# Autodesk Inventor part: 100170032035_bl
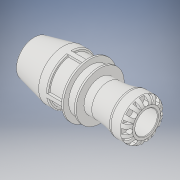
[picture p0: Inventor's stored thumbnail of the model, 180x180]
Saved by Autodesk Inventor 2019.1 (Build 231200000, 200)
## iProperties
Created: 2016-12
Part Number: 100170032035_bl
Material: PVC-Piping
Description: PLASSON UNIVERSAL COUPLING 31-35x32 SERIES 1
Document SubType Name: Modeling
Designer: KIM
Mass: 298.996 g
Surface Area: 569.061 cm^2
Volume: 213.568 cm^3
Density: 1.4 g/cm^3
Appearance: Smooth - White
Author: KIM
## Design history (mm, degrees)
derived "10017.ipt"
feature "Solid1::10017.ipt" dims "ScaleForDerivedMember" = 10
tag "TaggingFeature1"
body "Solid1"
other parameters: "d15" = 35 [user parameter], "d16" = 34.3 [user parameter], "d20" = 62.32 [user parameter], "d21" = 80 deg [user parameter], "d22" = 23 [user parameter], "d23" = 0 [user parameter], "d25" = 360 deg [user parameter], "d48" = 1.6 [user parameter], "d52" = 0.76 [user parameter], "d72" = 32 [user parameter], "d73" = 55 [user parameter], "d74" = 3.2 [user parameter], "d80" = 23.1 [user parameter], "d81" = 77 deg [user parameter], "d82" = 161 [user parameter], "d83" = 80.5 [user parameter], "d85" = 3.66667 [user parameter], "d86" = 76 [user parameter], "d87" = 69.92 [user parameter], "d88" = 57.6 [user parameter], "d89" = 12 [user parameter], "d90" = 60.8 [user parameter], "d91" = 46.08 [user parameter], "d93" = 1.61 [user parameter], "d96" = 7.04 [user parameter], "d97" = 7.04 [user parameter], "d98" = 0 [user parameter], "d100" = 360 deg [user parameter], "d103" = 0.64 [user parameter], "d104" = 0.64 [user parameter], "d105" = 8 deg [user parameter], "d106" = 8 deg [user parameter], "d108" = 0 [user parameter], "d110" = 360 deg [user parameter], "d112" = 9.6 [user parameter], "d113" = 4.8 [user parameter], "d115" = 44 [user parameter], "d116" = 0 [user parameter], "d118" = 360 deg [user parameter], "d120" = 7.6 [user parameter], "d121" = 0.76 [user parameter], "d_" = 32 [user parameter], "E_" = 76 [user parameter], "H_" = 161 [user parameter], "l_" = 55 [user parameter], "d_1" = 35 [user parameter], "d66" = 76 [user parameter], "d68" = 41 [user parameter], "d69" = 45 [user parameter], "d70" = 20.955 [user parameter], "d71" = 13 [user parameter], "d92" = 8.8 [user parameter], "d94" = 57.6 [user parameter]
